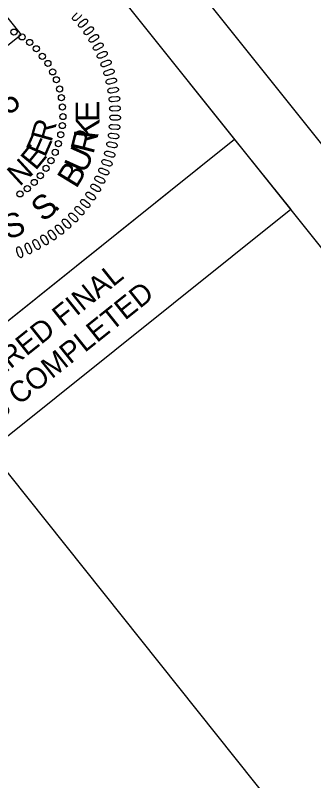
# Model space of a CAD drawing. Extents: x 472510 to 474509, y 505091 to 506998.
# Drawn here: x 473861.9 to 473939.9, y 506685.1 to 506885.2 of the extents above; entities that cross this region are included whole.
import ezdxf

# ---------------------------------------------------------------- set-up
doc = ezdxf.new("R2010")
doc.units = 0
for name, color, linetype in [('Sheet Clip Boundary CELL', 7, 'Continuous'), ('Sheet PE Seal Cell', 7, 'Continuous'), ('Sheet Plan CELL', 7, 'Continuous'), ('Sheet Plot Border Outside CELL', 7, 'Continuous'), ('Sheet Sticker Exception Certification CELL', 7, 'Continuous'), ('Sheet Sticker Incomplete CELL', 7, 'Continuous')]:
    doc.layers.add(name, color=color, linetype=linetype)

msp = doc.modelspace()

# ---------------------------------------------------------------- linework, layer by layer
at = {"layer": 'Sheet Clip Boundary CELL'}
msp.add_lwpolyline([(473777.72, 506709.45), (473669.28, 506844.95), (472855.07, 506193.32), (472968.62, 506051.1), (472829.89, 505940.08), (472768.98, 505889.4), (473229.88, 505313.51), (473287.27, 505310.53), (473108.82, 505533.5), (473372.02, 505744.15), (473550.47, 505521.18), (474139.22, 505988.54), (474128.73, 506014.5), (474324.31, 506183.29), (473855.21, 506771.46)], close=True, dxfattribs=at)
at = {"layer": 'Sheet PE Seal Cell'}
msp.add_lwpolyline([(473879.17, 506885.32), (473879.1, 506885.17), (473879.01, 506885), (473878.91, 506884.88), (473877.98, 506884.03), (473877.84, 506883.93), (473877.71, 506883.87), (473877.53, 506883.83), (473877.35, 506883.82), (473877.23, 506883.84), (473877.08, 506883.91), (473876.96, 506884.01), (473876.89, 506884.15), (473876.86, 506884.26), (473876.85, 506884.42), (473876.89, 506884.62), (473876.98, 506884.79), (473877.05, 506884.9), (473877.14, 506885), (473878.05, 506885.83)], dxfattribs=at)
for points in [[(473878.71, 506883.28), (473879.67, 506884.04), (473879.87, 506884.15), (473880.01, 506884.2), (473880.21, 506884.21), (473880.36, 506884.21), (473880.49, 506884.17), (473880.58, 506884.11), (473880.67, 506884.04), (473880.72, 506883.94), (473880.78, 506883.82), (473880.79, 506883.71), (473880.78, 506883.56), (473880.76, 506883.47), (473880.68, 506883.32), (473880.58, 506883.16), (473880.47, 506883.04), (473879.49, 506882.25), (473879.35, 506882.16), (473879.21, 506882.11), (473879.03, 506882.08), (473878.85, 506882.08), (473878.73, 506882.11), (473878.58, 506882.19), (473878.47, 506882.3), (473878.41, 506882.44), (473878.38, 506882.55), (473878.38, 506882.71), (473878.44, 506882.91), (473878.54, 506883.08), (473878.62, 506883.18)], [(473880.21, 506881.35), (473881.22, 506882.05), (473881.42, 506882.15), (473881.56, 506882.19), (473881.76, 506882.19), (473881.91, 506882.18), (473882.04, 506882.13), (473882.13, 506882.07), (473882.21, 506881.99), (473882.26, 506881.88), (473882.31, 506881.77), (473882.32, 506881.65), (473882.29, 506881.51), (473882.26, 506881.41), (473882.18, 506881.27), (473882.07, 506881.12), (473881.95, 506881.01), (473880.93, 506880.28), (473880.77, 506880.2), (473880.63, 506880.16), (473880.45, 506880.14), (473880.27, 506880.15), (473880.15, 506880.18), (473880.01, 506880.28), (473879.91, 506880.39), (473879.86, 506880.53), (473879.84, 506880.65), (473879.85, 506880.81), (473879.92, 506881.01), (473880.03, 506881.16), (473880.11, 506881.26)], [(473881.54, 506879.42), (473882.59, 506880.06), (473882.8, 506880.14), (473882.94, 506880.17), (473883.15, 506880.16), (473883.29, 506880.14), (473883.42, 506880.08), (473883.51, 506880.01), (473883.58, 506879.93), (473883.62, 506879.82), (473883.66, 506879.7), (473883.66, 506879.58), (473883.63, 506879.44), (473883.6, 506879.35), (473883.5, 506879.22), (473883.38, 506879.07), (473883.26, 506878.97), (473882.19, 506878.31), (473882.03, 506878.24), (473881.89, 506878.2), (473881.71, 506878.2), (473881.53, 506878.22), (473881.41, 506878.26), (473881.28, 506878.36), (473881.18, 506878.48), (473881.14, 506878.63), (473881.13, 506878.74), (473881.15, 506878.9), (473881.23, 506879.09), (473881.35, 506879.25), (473881.44, 506879.34)], [(473882.73, 506877.31), (473883.81, 506877.88), (473884.02, 506877.95), (473884.17, 506877.97), (473884.37, 506877.95), (473884.51, 506877.91), (473884.64, 506877.85), (473884.72, 506877.78), (473884.79, 506877.69), (473884.83, 506877.58), (473884.86, 506877.46), (473884.85, 506877.34), (473884.81, 506877.2), (473884.77, 506877.11), (473884.67, 506876.98), (473884.54, 506876.84), (473884.41, 506876.75), (473883.3, 506876.16), (473883.14, 506876.1), (473882.99, 506876.07), (473882.81, 506876.08), (473882.64, 506876.11), (473882.52, 506876.16), (473882.39, 506876.27), (473882.31, 506876.39), (473882.27, 506876.54), (473882.27, 506876.66), (473882.3, 506876.82), (473882.39, 506877), (473882.52, 506877.15), (473882.62, 506877.23)], [(473883.79, 506875.21), (473884.91, 506875.71), (473885.12, 506875.77), (473885.27, 506875.78), (473885.47, 506875.75), (473885.61, 506875.7), (473885.73, 506875.63), (473885.81, 506875.56), (473885.87, 506875.46), (473885.9, 506875.35), (473885.92, 506875.23), (473885.91, 506875.11), (473885.86, 506874.97), (473885.81, 506874.89), (473885.7, 506874.76), (473885.57, 506874.64), (473885.43, 506874.55), (473884.29, 506874.03), (473884.12, 506873.98), (473883.98, 506873.96), (473883.8, 506873.98), (473883.62, 506874.02), (473883.51, 506874.08), (473883.39, 506874.2), (473883.31, 506874.32), (473883.29, 506874.48), (473883.29, 506874.59), (473883.33, 506874.75), (473883.43, 506874.93), (473883.57, 506875.06), (473883.67, 506875.14)], [(473884.82, 506873.01), (473885.97, 506873.44), (473886.18, 506873.48), (473886.33, 506873.48), (473886.53, 506873.44), (473886.67, 506873.38), (473886.78, 506873.31), (473886.86, 506873.22), (473886.92, 506873.13), (473886.94, 506873.01), (473886.95, 506872.89), (473886.93, 506872.77), (473886.87, 506872.64), (473886.82, 506872.55), (473886.7, 506872.44), (473886.56, 506872.32), (473886.42, 506872.24), (473885.24, 506871.79), (473885.08, 506871.75), (473884.93, 506871.75), (473884.75, 506871.77), (473884.58, 506871.83), (473884.47, 506871.89), (473884.36, 506872.02), (473884.29, 506872.15), (473884.27, 506872.3), (473884.28, 506872.42), (473884.33, 506872.57), (473884.45, 506872.75), (473884.59, 506872.87), (473884.7, 506872.95)], [(473885.62, 506870.73), (473886.79, 506871.09), (473887.01, 506871.11), (473887.16, 506871.11), (473887.35, 506871.05), (473887.49, 506870.99), (473887.6, 506870.9), (473887.66, 506870.82), (473887.72, 506870.71), (473887.73, 506870.6), (473887.74, 506870.48), (473887.71, 506870.36), (473887.65, 506870.23), (473887.59, 506870.15), (473887.46, 506870.04), (473887.31, 506869.93), (473887.16, 506869.86), (473885.96, 506869.49), (473885.8, 506869.46), (473885.65, 506869.46), (473885.47, 506869.5), (473885.3, 506869.57), (473885.2, 506869.64), (473885.1, 506869.77), (473885.03, 506869.91), (473885.03, 506870.06), (473885.04, 506870.18), (473885.1, 506870.33), (473885.23, 506870.49), (473885.38, 506870.61), (473885.5, 506870.67)], [(473886.22, 506868.5), (473887.41, 506868.78), (473887.63, 506868.8), (473887.78, 506868.78), (473887.97, 506868.71), (473888.1, 506868.64), (473888.21, 506868.55), (473888.27, 506868.46), (473888.31, 506868.35), (473888.32, 506868.24), (473888.32, 506868.12), (473888.29, 506868), (473888.21, 506867.87), (473888.15, 506867.8), (473888.02, 506867.7), (473887.86, 506867.6), (473887.71, 506867.54), (473886.49, 506867.24), (473886.32, 506867.22), (473886.17, 506867.23), (473886, 506867.28), (473885.84, 506867.36), (473885.74, 506867.44), (473885.64, 506867.57), (473885.59, 506867.72), (473885.59, 506867.87), (473885.61, 506867.98), (473885.68, 506868.13), (473885.82, 506868.29), (473885.98, 506868.39), (473886.1, 506868.45)], [(473886.74, 506866.16), (473887.95, 506866.37), (473888.17, 506866.38), (473888.32, 506866.35), (473888.51, 506866.27), (473888.63, 506866.19), (473888.73, 506866.09), (473888.79, 506866), (473888.83, 506865.89), (473888.82, 506865.78), (473888.82, 506865.65), (473888.77, 506865.54), (473888.69, 506865.42), (473888.63, 506865.35), (473888.49, 506865.25), (473888.32, 506865.16), (473888.17, 506865.12), (473886.93, 506864.89), (473886.76, 506864.89), (473886.62, 506864.91), (473886.44, 506864.97), (473886.29, 506865.05), (473886.19, 506865.14), (473886.11, 506865.28), (473886.06, 506865.42), (473886.08, 506865.58), (473886.11, 506865.69), (473886.18, 506865.83), (473886.33, 506865.98), (473886.5, 506866.08), (473886.62, 506866.13)], [(473887.11, 506863.88), (473888.33, 506864.02), (473888.55, 506864), (473888.7, 506863.97), (473888.88, 506863.87), (473889, 506863.79), (473889.09, 506863.69), (473889.14, 506863.59), (473889.17, 506863.48), (473889.17, 506863.36), (473889.15, 506863.24), (473889.1, 506863.13), (473889.01, 506863.02), (473888.94, 506862.95), (473888.8, 506862.87), (473888.63, 506862.79), (473888.47, 506862.75), (473887.22, 506862.6), (473887.05, 506862.61), (473886.91, 506862.64), (473886.74, 506862.71), (473886.59, 506862.8), (473886.5, 506862.89), (473886.42, 506863.04), (473886.39, 506863.19), (473886.41, 506863.34), (473886.45, 506863.45), (473886.53, 506863.59), (473886.69, 506863.72), (473886.86, 506863.81), (473886.98, 506863.85)], [(473887.31, 506861.46), (473888.53, 506861.52), (473888.76, 506861.49), (473888.9, 506861.44), (473889.07, 506861.34), (473889.19, 506861.25), (473889.27, 506861.14), (473889.32, 506861.04), (473889.34, 506860.93), (473889.33, 506860.81), (473889.3, 506860.69), (473889.25, 506860.58), (473889.15, 506860.48), (473889.07, 506860.41), (473888.93, 506860.34), (473888.75, 506860.27), (473888.59, 506860.24), (473887.34, 506860.17), (473887.17, 506860.19), (473887.03, 506860.23), (473886.86, 506860.31), (473886.72, 506860.41), (473886.63, 506860.51), (473886.57, 506860.66), (473886.54, 506860.81), (473886.57, 506860.96), (473886.62, 506861.07), (473886.71, 506861.2), (473886.88, 506861.33), (473887.05, 506861.4), (473887.18, 506861.44)], [(473887.39, 506859.11), (473888.61, 506859.09), (473888.83, 506859.05), (473888.97, 506859), (473889.14, 506858.88), (473889.25, 506858.78), (473889.33, 506858.67), (473889.36, 506858.57), (473889.38, 506858.45), (473889.36, 506858.34), (473889.33, 506858.22), (473889.27, 506858.12), (473889.16, 506858.02), (473889.08, 506857.96), (473888.93, 506857.89), (473888.75, 506857.84), (473888.59, 506857.82), (473887.34, 506857.83), (473887.17, 506857.85), (473887.03, 506857.9), (473886.87, 506857.99), (473886.73, 506858.11), (473886.65, 506858.21), (473886.6, 506858.36), (473886.58, 506858.51), (473886.62, 506858.66), (473886.67, 506858.77), (473886.78, 506858.89), (473886.95, 506859.01), (473887.13, 506859.07), (473887.26, 506859.1)], [(473887.27, 506856.7), (473888.5, 506856.61), (473888.71, 506856.55), (473888.85, 506856.49), (473889.01, 506856.36), (473889.11, 506856.26), (473889.18, 506856.14), (473889.21, 506856.03), (473889.22, 506855.92), (473889.19, 506855.81), (473889.15, 506855.69), (473889.09, 506855.59), (473888.98, 506855.5), (473888.89, 506855.44), (473888.74, 506855.39), (473888.56, 506855.34), (473888.4, 506855.33), (473887.14, 506855.42), (473886.98, 506855.46), (473886.84, 506855.52), (473886.69, 506855.62), (473886.56, 506855.74), (473886.49, 506855.84), (473886.44, 506856), (473886.43, 506856.16), (473886.48, 506856.3), (473886.54, 506856.4), (473886.65, 506856.52), (473886.83, 506856.63), (473887.01, 506856.68), (473887.14, 506856.7)], [(473887.07, 506854.37), (473888.29, 506854.2), (473888.5, 506854.13), (473888.63, 506854.06), (473888.78, 506853.93), (473888.88, 506853.81), (473888.94, 506853.69), (473888.97, 506853.58), (473888.97, 506853.47), (473888.93, 506853.36), (473888.89, 506853.25), (473888.81, 506853.15), (473888.7, 506853.06), (473888.61, 506853.01), (473888.45, 506852.97), (473888.27, 506852.93), (473888.11, 506852.93), (473886.86, 506853.1), (473886.7, 506853.15), (473886.57, 506853.22), (473886.42, 506853.33), (473886.3, 506853.46), (473886.23, 506853.57), (473886.2, 506853.73), (473886.2, 506853.88), (473886.26, 506854.02), (473886.32, 506854.12), (473886.44, 506854.23), (473886.62, 506854.32), (473886.81, 506854.37), (473886.94, 506854.38)], [(473886.68, 506852.1), (473887.88, 506851.85), (473888.09, 506851.77), (473888.21, 506851.69), (473888.35, 506851.54), (473888.44, 506851.42), (473888.5, 506851.3), (473888.52, 506851.19), (473888.51, 506851.07), (473888.47, 506850.97), (473888.42, 506850.86), (473888.34, 506850.77), (473888.22, 506850.69), (473888.13, 506850.64), (473887.97, 506850.61), (473887.78, 506850.59), (473887.62, 506850.6), (473886.39, 506850.84), (473886.22, 506850.9), (473886.1, 506850.97), (473885.96, 506851.09), (473885.85, 506851.23), (473885.79, 506851.34), (473885.76, 506851.51), (473885.77, 506851.66), (473885.84, 506851.8), (473885.91, 506851.89), (473886.03, 506851.99), (473886.22, 506852.08), (473886.41, 506852.11), (473886.55, 506852.11)], [(473886.17, 506849.68), (473887.35, 506849.36), (473887.55, 506849.26), (473887.67, 506849.18), (473887.81, 506849.02), (473887.89, 506848.9), (473887.93, 506848.77), (473887.94, 506848.66), (473887.93, 506848.55), (473887.88, 506848.45), (473887.82, 506848.34), (473887.74, 506848.25), (473887.61, 506848.18), (473887.52, 506848.14), (473887.36, 506848.12), (473887.17, 506848.11), (473887.01, 506848.13), (473885.8, 506848.45), (473885.64, 506848.52), (473885.52, 506848.6), (473885.39, 506848.73), (473885.28, 506848.87), (473885.23, 506848.99), (473885.21, 506849.15), (473885.24, 506849.3), (473885.31, 506849.44), (473885.39, 506849.53), (473885.52, 506849.62), (473885.71, 506849.69), (473885.91, 506849.71), (473886.04, 506849.7)], [(473885.48, 506847.43), (473886.64, 506847.03), (473886.83, 506846.93), (473886.95, 506846.83), (473887.07, 506846.67), (473887.15, 506846.54), (473887.19, 506846.41), (473887.19, 506846.3), (473887.17, 506846.19), (473887.12, 506846.09), (473887.05, 506845.98), (473886.96, 506845.9), (473886.83, 506845.84), (473886.74, 506845.81), (473886.57, 506845.79), (473886.38, 506845.79), (473886.22, 506845.82), (473885.03, 506846.23), (473884.88, 506846.3), (473884.76, 506846.39), (473884.64, 506846.53), (473884.55, 506846.68), (473884.5, 506846.8), (473884.5, 506846.96), (473884.53, 506847.11), (473884.61, 506847.24), (473884.69, 506847.32), (473884.83, 506847.41), (473885.03, 506847.47), (473885.22, 506847.47), (473885.35, 506847.46)], [(473884.69, 506845.19), (473885.82, 506844.72), (473886.01, 506844.6), (473886.12, 506844.5), (473886.23, 506844.33), (473886.3, 506844.2), (473886.33, 506844.06), (473886.32, 506843.95), (473886.3, 506843.84), (473886.24, 506843.75), (473886.16, 506843.65), (473886.07, 506843.57), (473885.94, 506843.51), (473885.84, 506843.49), (473885.68, 506843.48), (473885.49, 506843.5), (473885.33, 506843.54), (473884.17, 506844.01), (473884.02, 506844.1), (473883.91, 506844.2), (473883.79, 506844.34), (473883.71, 506844.5), (473883.67, 506844.62), (473883.68, 506844.78), (473883.72, 506844.93), (473883.81, 506845.05), (473883.9, 506845.13), (473884.04, 506845.21), (473884.24, 506845.25), (473884.43, 506845.25), (473884.56, 506845.23)], [(473883.71, 506843.05), (473884.81, 506842.5), (473884.99, 506842.38), (473885.1, 506842.27), (473885.2, 506842.09), (473885.25, 506841.96), (473885.28, 506841.82), (473885.27, 506841.71), (473885.23, 506841.6), (473885.17, 506841.51), (473885.09, 506841.41), (473884.99, 506841.34), (473884.85, 506841.3), (473884.75, 506841.28), (473884.59, 506841.28), (473884.4, 506841.31), (473884.25, 506841.36), (473883.12, 506841.91), (473882.98, 506842), (473882.87, 506842.1), (473882.77, 506842.25), (473882.69, 506842.41), (473882.66, 506842.54), (473882.68, 506842.7), (473882.73, 506842.85), (473882.83, 506842.96), (473882.92, 506843.04), (473883.06, 506843.11), (473883.27, 506843.14), (473883.46, 506843.12), (473883.59, 506843.09)], [(473882.68, 506840.93), (473883.74, 506840.32), (473883.92, 506840.18), (473884.01, 506840.07), (473884.1, 506839.88), (473884.15, 506839.75), (473884.16, 506839.61), (473884.15, 506839.5), (473884.11, 506839.39), (473884.04, 506839.3), (473883.95, 506839.21), (473883.85, 506839.15), (473883.71, 506839.11), (473883.61, 506839.1), (473883.45, 506839.11), (473883.26, 506839.15), (473883.11, 506839.21), (473882.02, 506839.83), (473881.88, 506839.93), (473881.78, 506840.04), (473881.69, 506840.2), (473881.62, 506840.36), (473881.6, 506840.49), (473881.62, 506840.65), (473881.68, 506840.79), (473881.79, 506840.9), (473881.89, 506840.97), (473882.04, 506841.03), (473882.24, 506841.05), (473882.43, 506841.02), (473882.56, 506840.98)], [(473881.43, 506838.83), (473882.45, 506838.15), (473882.61, 506838), (473882.7, 506837.88), (473882.78, 506837.69), (473882.82, 506837.55), (473882.82, 506837.41), (473882.8, 506837.31), (473882.76, 506837.2), (473882.68, 506837.12), (473882.59, 506837.03), (473882.48, 506836.98), (473882.34, 506836.95), (473882.24, 506836.94), (473882.08, 506836.97), (473881.89, 506837.02), (473881.75, 506837.09), (473880.69, 506837.77), (473880.57, 506837.88), (473880.47, 506838), (473880.39, 506838.16), (473880.33, 506838.33), (473880.32, 506838.45), (473880.36, 506838.62), (473880.42, 506838.75), (473880.54, 506838.86), (473880.64, 506838.92), (473880.79, 506838.97), (473881, 506838.97), (473881.19, 506838.93), (473881.31, 506838.89)], [(473880.06, 506836.87), (473881.04, 506836.13), (473881.19, 506835.97), (473881.27, 506835.85), (473881.34, 506835.65), (473881.37, 506835.51), (473881.36, 506835.37), (473881.33, 506835.27), (473881.28, 506835.16), (473881.2, 506835.09), (473881.1, 506835.01), (473880.99, 506834.96), (473880.85, 506834.94), (473880.75, 506834.94), (473880.59, 506834.97), (473880.41, 506835.03), (473880.27, 506835.11), (473879.26, 506835.86), (473879.14, 506835.98), (473879.05, 506836.1), (473878.98, 506836.27), (473878.94, 506836.44), (473878.93, 506836.57), (473878.98, 506836.73), (473879.05, 506836.86), (473879.17, 506836.96), (473879.28, 506837.01), (473879.43, 506837.05), (473879.64, 506837.04), (473879.82, 506836.99), (473879.94, 506836.94)], [(473877.06, 506833.26), (473877.94, 506832.4), (473878.07, 506832.22), (473878.13, 506832.09), (473878.18, 506831.89), (473878.19, 506831.74), (473878.17, 506831.61), (473878.12, 506831.5), (473878.06, 506831.41), (473877.97, 506831.34), (473877.86, 506831.28), (473877.75, 506831.24), (473877.6, 506831.24), (473877.5, 506831.25), (473877.35, 506831.31), (473877.18, 506831.39), (473877.05, 506831.48), (473876.14, 506832.35), (473876.03, 506832.49), (473875.97, 506832.62), (473875.91, 506832.79), (473875.89, 506832.97), (473875.9, 506833.1), (473875.97, 506833.25), (473876.06, 506833.37), (473876.19, 506833.45), (473876.3, 506833.49), (473876.46, 506833.51), (473876.66, 506833.48), (473876.84, 506833.4), (473876.95, 506833.34)], [(473878.61, 506835.02), (473879.54, 506834.22), (473879.68, 506834.05), (473879.76, 506833.92), (473879.81, 506833.73), (473879.83, 506833.58), (473879.82, 506833.45), (473879.78, 506833.34), (473879.72, 506833.24), (473879.63, 506833.17), (473879.53, 506833.1), (473879.42, 506833.06), (473879.28, 506833.04), (473879.18, 506833.05), (473879.02, 506833.1), (473878.85, 506833.17), (473878.71, 506833.25), (473877.75, 506834.06), (473877.64, 506834.19), (473877.56, 506834.32), (473877.5, 506834.49), (473877.46, 506834.66), (473877.46, 506834.79), (473877.52, 506834.95), (473877.6, 506835.08), (473877.73, 506835.16), (473877.84, 506835.21), (473878, 506835.24), (473878.2, 506835.22), (473878.38, 506835.16), (473878.5, 506835.1)], [(473875.33, 506831.63), (473876.16, 506830.72), (473876.28, 506830.53), (473876.33, 506830.39), (473876.36, 506830.19), (473876.36, 506830.04), (473876.33, 506829.91), (473876.28, 506829.81), (473876.21, 506829.72), (473876.12, 506829.66), (473876.01, 506829.6), (473875.89, 506829.58), (473875.75, 506829.58), (473875.65, 506829.6), (473875.5, 506829.66), (473875.33, 506829.76), (473875.21, 506829.86), (473874.36, 506830.78), (473874.26, 506830.92), (473874.2, 506831.06), (473874.16, 506831.24), (473874.15, 506831.42), (473874.17, 506831.54), (473874.24, 506831.69), (473874.34, 506831.8), (473874.48, 506831.88), (473874.59, 506831.91), (473874.75, 506831.92), (473874.95, 506831.88), (473875.12, 506831.79), (473875.23, 506831.71)], [(473873.56, 506830.05), (473874.33, 506829.09), (473874.43, 506828.9), (473874.48, 506828.76), (473874.5, 506828.55), (473874.49, 506828.41), (473874.45, 506828.28), (473874.4, 506828.18), (473874.32, 506828.09), (473874.22, 506828.04), (473874.11, 506827.99), (473873.99, 506827.97), (473873.85, 506827.98), (473873.75, 506828.01), (473873.6, 506828.08), (473873.44, 506828.18), (473873.33, 506828.29), (473872.54, 506829.27), (473872.45, 506829.42), (473872.4, 506829.56), (473872.37, 506829.74), (473872.37, 506829.91), (473872.39, 506830.04), (473872.48, 506830.18), (473872.58, 506830.29), (473872.72, 506830.35), (473872.84, 506830.38), (473873, 506830.38), (473873.2, 506830.32), (473873.36, 506830.23), (473873.47, 506830.14)], [(473869.75, 506827.34), (473870.38, 506826.3), (473870.47, 506826.09), (473870.5, 506825.94), (473870.49, 506825.74), (473870.46, 506825.6), (473870.41, 506825.47), (473870.34, 506825.38), (473870.26, 506825.31), (473870.15, 506825.26), (473870.03, 506825.23), (473869.91, 506825.22), (473869.77, 506825.25), (473869.68, 506825.29), (473869.54, 506825.38), (473869.4, 506825.51), (473869.29, 506825.63), (473868.63, 506826.7), (473868.56, 506826.85), (473868.53, 506827), (473868.52, 506827.18), (473868.54, 506827.36), (473868.59, 506827.48), (473868.69, 506827.61), (473868.81, 506827.7), (473868.95, 506827.75), (473869.07, 506827.76), (473869.23, 506827.74), (473869.42, 506827.66), (473869.57, 506827.54), (473869.66, 506827.45)], [(473871.68, 506828.64), (473872.38, 506827.63), (473872.48, 506827.43), (473872.52, 506827.29), (473872.52, 506827.08), (473872.5, 506826.94), (473872.46, 506826.81), (473872.4, 506826.72), (473872.31, 506826.64), (473872.21, 506826.59), (473872.1, 506826.54), (473871.98, 506826.53), (473871.83, 506826.55), (473871.74, 506826.58), (473871.6, 506826.67), (473871.45, 506826.78), (473871.34, 506826.9), (473870.61, 506827.92), (473870.53, 506828.07), (473870.49, 506828.21), (473870.47, 506828.4), (473870.48, 506828.58), (473870.51, 506828.7), (473870.61, 506828.84), (473870.72, 506828.94), (473870.86, 506828.99), (473870.98, 506829.01), (473871.14, 506829), (473871.33, 506828.93), (473871.49, 506828.82), (473871.59, 506828.73)], [(473864.45, 506824.53), (473864.96, 506823.41), (473865.08, 506823.23), (473865.18, 506823.12), (473865.36, 506823.02), (473865.49, 506822.96), (473865.63, 506822.93), (473865.74, 506822.94), (473865.85, 506822.96), (473865.94, 506823.03), (473866.04, 506823.11), (473866.11, 506823.2), (473866.16, 506823.34), (473866.19, 506823.43), (473866.19, 506823.6), (473866.17, 506823.79), (473866.12, 506823.94), (473865.61, 506825.09), (473865.52, 506825.23), (473865.42, 506825.34), (473865.28, 506825.45), (473865.12, 506825.53), (473865, 506825.57), (473864.83, 506825.56), (473864.68, 506825.51), (473864.56, 506825.41), (473864.49, 506825.33), (473864.41, 506825.18), (473864.37, 506824.98), (473864.39, 506824.79), (473864.41, 506824.66)], [(473867.69, 506826.12), (473868.27, 506825.03), (473868.34, 506824.82), (473868.36, 506824.68), (473868.34, 506824.47), (473868.3, 506824.33), (473868.24, 506824.21), (473868.17, 506824.12), (473868.08, 506824.05), (473867.97, 506824.02), (473867.85, 506823.99), (473867.73, 506823.99), (473867.59, 506824.03), (473867.5, 506824.08), (473867.37, 506824.18), (473867.23, 506824.31), (473867.14, 506824.44), (473866.54, 506825.55), (473866.48, 506825.71), (473866.46, 506825.85), (473866.46, 506826.03), (473866.5, 506826.21), (473866.55, 506826.33), (473866.66, 506826.45), (473866.78, 506826.54), (473866.93, 506826.57), (473867.05, 506826.58), (473867.2, 506826.55), (473867.39, 506826.45), (473867.53, 506826.33), (473867.62, 506826.23)], [(473862.21, 506823.6), (473862.64, 506822.45), (473862.76, 506822.26), (473862.85, 506822.15), (473863.02, 506822.03), (473863.15, 506821.96), (473863.28, 506821.93), (473863.39, 506821.93), (473863.5, 506821.95), (473863.6, 506822.01), (473863.7, 506822.08), (473863.78, 506822.17), (473863.84, 506822.3), (473863.87, 506822.39), (473863.88, 506822.56), (473863.87, 506822.75), (473863.84, 506822.9), (473863.4, 506824.08), (473863.32, 506824.23), (473863.23, 506824.35), (473863.09, 506824.47), (473862.94, 506824.56), (473862.82, 506824.6), (473862.65, 506824.6), (473862.5, 506824.56), (473862.38, 506824.47), (473862.3, 506824.39), (473862.21, 506824.25), (473862.16, 506824.05), (473862.16, 506823.86), (473862.18, 506823.73)]]:
    msp.add_lwpolyline(points, close=True, dxfattribs=at)
for centre in [(473861.53, 506880.82), (473863.66, 506879.56), (473865.62, 506878.12), (473867.37, 506876.45), (473868.93, 506874.49), (473870.39, 506872.63), (473871.64, 506870.42), (473872.63, 506868.35), (473873.44, 506865.94), (473873.93, 506863.68), (473874.2, 506861.24), (473874.31, 506858.73), (473874.17, 506856.37), (473873.75, 506853.96), (473873.15, 506851.65), (473872.3, 506849.39), (473871.22, 506847.21), (473869.92, 506845.21), (473868.43, 506843.25), (473866.82, 506841.5), (473865, 506839.89), (473863.09, 506838.52)]:
    msp.add_circle(centre, 0.801, dxfattribs=at)
at = {"layer": 'Sheet Plan CELL'}
for points in [[(473825.47, 506969.95), (472654.33, 506032.66), (473310.42, 505212.87), (474481.55, 506150.16)], [(473770.85, 506878.13), (473848.91, 506940.61), (473919.22, 506852.78), (473841.16, 506790.28)]]:
    msp.add_lwpolyline(points, close=True, dxfattribs=at)
at = {"layer": 'Sheet Plot Border Outside CELL'}
msp.add_lwpolyline([(473194.51, 505091.27), (474508.89, 506143.2), (473824.68, 506998.12), (472510.29, 505946.18)], close=True, dxfattribs=at)
at = {"layer": 'Sheet Sticker Exception Certification CELL'}
for p, q in [((473763.04, 506727.79), (473919.21, 506852.79)), ((473763.04, 506727.79), (473919.21, 506852.79)), ((473919.22, 506852.78), (473933.91, 506834.43)), ((473919.22, 506852.78), (473933.91, 506834.43)), ((473933.9, 506834.44), (473777.72, 506709.45)), ((473933.9, 506834.44), (473777.72, 506709.45))]:
    msp.add_line(p, q, dxfattribs=at)
at = {"layer": 'Sheet Sticker Incomplete CELL'}
msp.add_lwpolyline([(473748.62, 506788.28), (473733.93, 506806.63), (473848.7, 506898.48), (473863.38, 506880.14)], close=True, dxfattribs=at)

# ---------------------------------------------------------------- texts
at = {"layer": 'Sheet PE Seal Cell'}
for s, height, rotation, p in [('46155', 6.236, 38.6526, (473845.67, 506847.31)), ('E', 6.24, 89.9395, (473883.85, 506857.36)), ('R', 5.67, 74.3348, (473871.32, 506851.84)), ('K', 6.24, 83.0938, (473883.3, 506852.59)), ('E', 5.67, 66.395, (473869.65, 506847.87)), ('R', 6.24, 75.8188, (473882.27, 506848.71)), ('E', 5.67, 50.5154, (473867.18, 506844.45)), ('U', 6.24, 65.7189, (473880.11, 506843.56)), ('N', 5.67, 42.5756, (473862.99, 506840.32)), ('B', 6.24, 58.6021, (473877.8, 506839.69)), ('S', 6.24, 38.0538, (473869.12, 506831.01)), ('S', 6.24, 19.4586, (473859.77, 506826.5)), ('.', 6.24, 44.8995, (473872.3, 506833.5))]:
    msp.add_text(s, height=height, rotation=rotation, dxfattribs=at).set_placement(p)
at = {"layer": 'Sheet Sticker Exception Certification CELL'}
for s, p in [('DOCUMENT NOT CONSIDERED FINAL', (473785.95, 506732.88)), ('DOCUMENT NOT CONSIDERED FINAL', (473785.95, 506732.88)), ('UNLESS ALL SIGNATURES COMPLETED', (473787.49, 506722.84)), ('UNLESS ALL SIGNATURES COMPLETED', (473787.49, 506722.84))]:
    msp.add_text(s, height=5.5, rotation=38.6712, dxfattribs=at).set_placement(p)
at = {"layer": 'Sheet Sticker Incomplete CELL'}
msp.add_text('INCOMPLETE PLANS', height=11.52, rotation=38.6712, dxfattribs=at).set_placement((473748.29, 506803.01))

doc.saveas('drawing.dxf')
